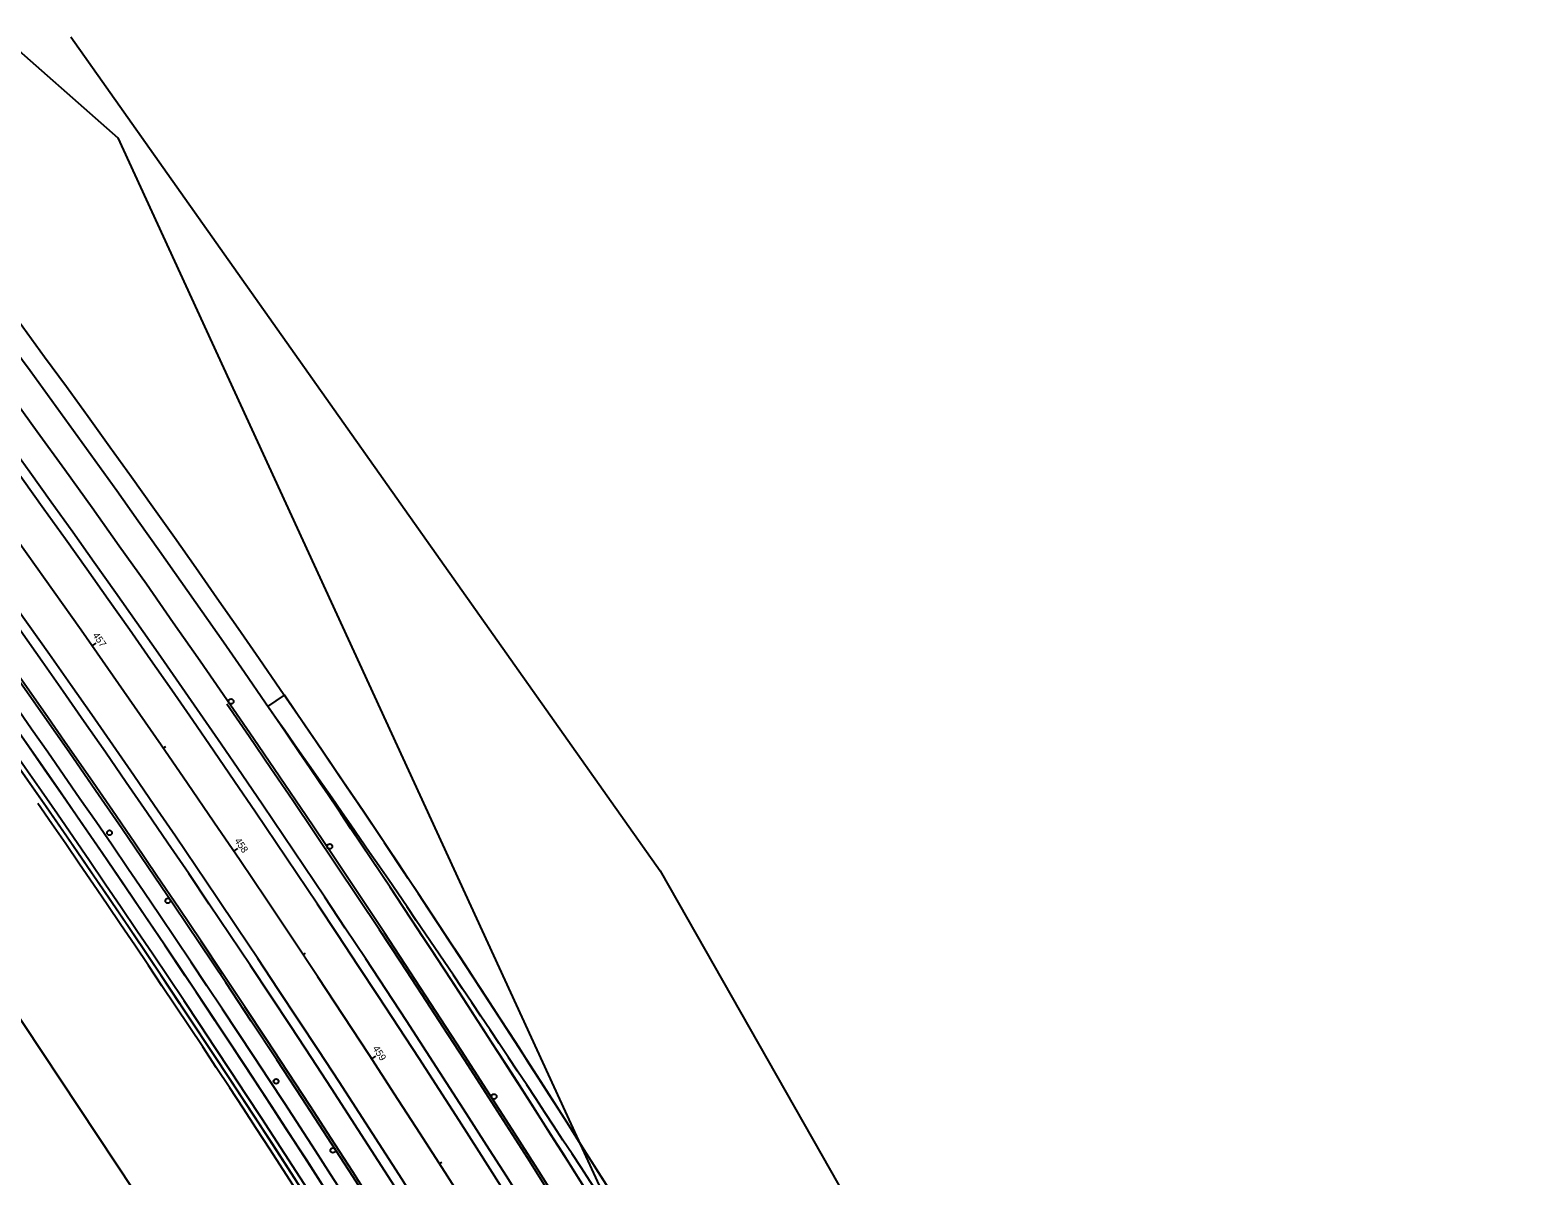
# Model space of a CAD drawing. Extents: x 7786 to 17579, y 337 to 8611.
# Drawn here: x 11209 to 11813, y 5143 to 5602 of the extents above; entities that cross this region are included whole.
import ezdxf

# ---------------------------------------------------------------- set-up
doc = ezdxf.new("R2010")
doc.units = 0
for name, color, linetype in [('GE_P_Alignment', 7, 'Continuous'), ('GE_P_Alignment_100_Stations', 7, 'Continuous'), ('MT_P_Edge_Line', 7, 'Continuous'), ('MT_P_Text', 7, 'Continuous'), ('PM_X_Lane_Line', 7, 'Continuous'), ('PV_P_EOP', 7, 'Continuous'), ('PV_P_Shoulder', 7, 'Continuous'), ('PV_X_EOP', 7, 'Continuous'), ('PV_X_Shoulder', 7, 'Continuous'), ('RD_X_GR_Rt', 7, 'Continuous'), ('RW_X_Esmt_LA', 7, 'Continuous')]:
    doc.layers.add(name, color=color, linetype=linetype)

msp = doc.modelspace()

# ---------------------------------------------------------------- linework, layer by layer
at = {"layer": 'GE_P_Alignment'}
for p, q in [((10072.42, 6590.16), (11244.05, 5559.32)), ((11244.05, 5559.32), (12302.66, 3255.22))]:
    msp.add_line(p, q, dxfattribs=at)
msp.add_arc((6545.73, 2061.51), 5729.58, 24.676389, 48.6575, dxfattribs=at)
msp.add_arc((6545.73, 2061.51), 5729.58, 24.676389, 48.6575, dxfattribs=at)
at = {"layer": 'GE_P_Alignment_100_Stations'}
for p, q in [((11233.7, 5355.59), (11235.34, 5356.74)), ((11262.27, 5314.56), (11263.26, 5315.24)), ((11262.27, 5314.56), (11263.26, 5315.24)), ((11290.48, 5273.28), (11292.13, 5274.4)), ((11318.32, 5231.75), (11319.32, 5232.41)), ((11318.32, 5231.75), (11319.32, 5232.41)), ((11345.81, 5189.98), (11347.48, 5191.07)), ((11372.92, 5147.97), (11373.94, 5148.62)), ((11372.92, 5147.97), (11373.94, 5148.62))]:
    msp.add_line(p, q, dxfattribs=at)
at = {"layer": 'MT_P_Edge_Line'}
for centre in [(11289.43, 5333.3), (11329, 5275.17), (11264.09, 5253.38), (11394.88, 5174.87), (11330.28, 5153.29)]:
    msp.add_circle(centre, 1, dxfattribs=at)
for radius, start, end in [(5698.58, 28.29546, 48.6575), (5760.58, 24.676389, 34.594405)]:
    msp.add_arc((6545.73, 2061.51), radius, start, end, dxfattribs=at)
at = {"layer": 'MT_P_Text'}
for centre in [(11240.69, 5280.63), (11307.51, 5180.96)]:
    msp.add_circle(centre, 1, dxfattribs=at)
for centre, radius, start, end in [((6545.73, 2061.51), 5690.58, 28.34441, 35.6444), ((6545.73, 2061.51), 5679.58, 28.34441, 35.6444), ((6592.52, 1994.31), 5773.58, 31.053521, 35.256126)]:
    msp.add_arc(centre, radius, start, end, dxfattribs=at)
at = {"layer": 'PM_X_Lane_Line'}
for radius, start in [(5761.58, 24.676389), (5697.58, 24.67639)]:
    msp.add_arc((6545.73, 2061.51), radius, start, 48.6575, dxfattribs=at)
at = {"layer": 'PV_P_EOP'}
for radius, start, end in [(5685.58, 29.60201, 47.0944), (5773.58, 29.790455, 34.494405)]:
    msp.add_arc((6545.73, 2061.51), radius, start, end, dxfattribs=at)
at = {"layer": 'PV_P_Shoulder'}
msp.add_line((11304.2, 5331.24), (11310.8, 5335.77), dxfattribs=at)
for radius, start, end in [(5677.58, 29.60201, 47.0944), (5781.58, 29.805871, 34.494405)]:
    msp.add_arc((6545.73, 2061.51), radius, start, end, dxfattribs=at)
at = {"layer": 'PV_X_EOP'}
for radius, start in [(5773.58, 29.790455), (5749.58, 29.743945), (5709.58, 29.66554), (5685.58, 29.61796)]:
    msp.add_arc((6545.73, 2061.51), radius, start, 48.6575, dxfattribs=at)
at = {"layer": 'PV_X_Shoulder'}
for radius, start in [(5781.58, 29.805871), (5745.58, 29.736155), (5713.58, 29.67343), (5677.58, 29.60201)]:
    msp.add_arc((6545.73, 2061.51), radius, start, 48.6575, dxfattribs=at)
at = {"layer": 'RD_X_GR_Rt'}
msp.add_arc((6545.73, 2061.51), 5675.58, 28.35494, 34.69774, dxfattribs=at)
at = {"layer": 'RW_X_Esmt_LA'}
msp.add_line((11225.16, 5599.82), (11461.42, 5265.33), dxfattribs=at)
for points in [[(11225.16, 5599.82), (11461.42, 5265.33), (11726.86, 4798.39), (12014, 4197.07)], [(11037.71, 5458.09), (11309.03, 5048.88), (11665.76, 4413.91), (11802.46, 4096.06)]]:
    msp.add_lwpolyline(points, dxfattribs=at)

# ---------------------------------------------------------------- texts
at = {"layer": 'GE_P_Alignment_100_Stations'}
for s, rotation, p in [('457', 305.0944, (11233.78, 5359.83)), ('458', 304.09441, (11290.68, 5277.44)), ('459', 303.09441, (11346.09, 5194.13))]:
    msp.add_text(s, height=2.8, rotation=rotation, dxfattribs=at).set_placement(p)

doc.saveas('drawing.dxf')
